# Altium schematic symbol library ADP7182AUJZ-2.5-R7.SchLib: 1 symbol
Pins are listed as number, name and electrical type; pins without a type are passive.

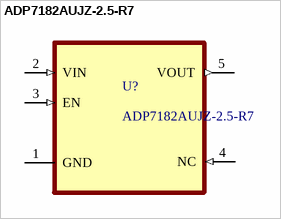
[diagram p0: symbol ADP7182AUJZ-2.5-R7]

## ADP7182AUJZ-2.5-R7
designator U?
Linear Voltage Regulator IC 1 Output -200mA -2.5V TSOT-5; MF: Analog Devices; MP: ADP121-AUJZ25R7
footprint ADP7182AUJZ-2.5-R7
pins: 1 GND, 2 VIN (in), 3 EN (in), 4 NC (in), 5 VOUT (out)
